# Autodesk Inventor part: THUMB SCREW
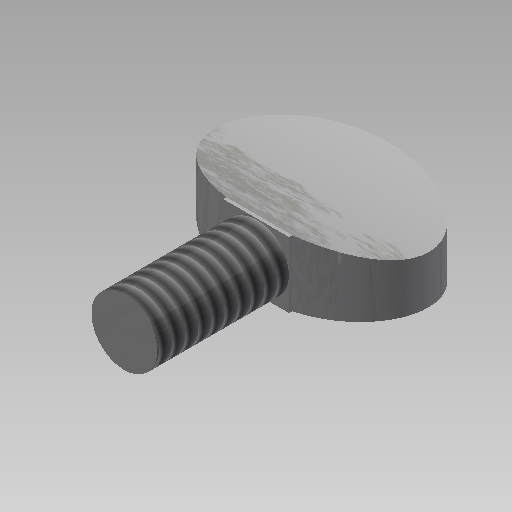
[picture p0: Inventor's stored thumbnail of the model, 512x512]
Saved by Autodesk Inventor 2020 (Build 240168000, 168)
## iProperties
Part Number: THUMB SCREW
Document SubType Name: Modeling
Created: 2003-11
Designer: Autodesk, Inc.
Manufacturer: Standard
Standards Organization: Custom
Mass: 11.3543 g
Surface Area: 9.71998 cm^2
Volume: 1.44641 cm^3
Density: 7.85 g/cm^3
Material: Steel, Mild
Appearance: Steel
Control State: 0
Master: False
Checked Out: False
Shininess: 64.0
Length Units: 11272
Angle Units: 11279
Time Units: 11290
Mass Units: 11286
Length Display Precision: 3
Angle Display Precision: 2
Compacted: True
Density: 0.0
Volumn: 0.0
Area: 0.0
PropertySet Name: Model Information
Author: Autodesk, Inc.
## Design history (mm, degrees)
sketch "Sketch1"
  geometry: C1 r 3.175 at (0, 0); 1 further point
  constraints: 1 centre point, 1 coincident
  dimensions: "d0" = 6.35 diameter of C1
extrude "Extrusion1" new body sketch "Sketch1" distance "d1" = 12.7; taper "d2" = 0 deg
sketch "Sketch2"
  geometry: L1 (-10.312, 3.175)-(10.312, 3.175); L2 (10.312, 3.175)-(10.312, -3.175); L3 (10.312, -3.175)-(-10.312, -3.175); L4 (-10.312, -3.175)-(-10.312, 3.175); C1 r 3.175 at (0, 0) reference; 1 further point
  constraints: 8 end point, 2 parallel, 1 horizontal, 1 perpendicular
  dimensions: "d3" = 3.175 distance from line of L3 point (0, 0); "d4" = 3.175 distance from line of point (0, 0) L1; "d5" = 20.6248 distance between parallel lines of L2 L4; "d6" = 10.3124 distance from line of L4 point (0, 0) (= 0.5 x d5)
extrude "Extrusion2" join sketch "Sketch2" distance "d7" = 12.7; taper "d8" = 0 deg
sketch "Sketch3"
  geometry: L1 (20.625, 12.7)-(0, 12.7) reference; L2 (0, 0)-(0, 12.7) reference; L3 (10.312, 0)-(0, 0) reference; L4 (20.625, 0)-(10.312, 0) reference; L5 (20.625, 0)-(20.625, 12.7) reference; L6 (10.312, 12.7)-(10.312, 0); L7 (0, 6.35)-(20.625, 6.35); L8 (7.137, 0)-(7.137, -12.7) reference; L9 (13.487, 0)-(13.487, -12.7) reference; L10 (7.137, 0)-(7.137, 0.308); L11 (13.487, 0)-(13.487, 0.308); 1 further point
  constraints: 8 end point, 4 midpoint, 3 vertical, 1 parallel, 6 other
extrude "Extrusion3" cut sketch "Sketch3" distance "d9" = 12.7; taper "d10" = 0 deg
workplane "Work Plane1"
sketch "Sketch4"
  geometry: L1 (-3.175, -0.308)-(-3.175, -0.308) reference; L2 (3.175, -0.308)-(-3.175, -0.308) reference; L3 (3.175, -0.308)-(3.175, -0.308) reference; L4 (3.175, -0.308)-(-3.175, -0.308) reference; L5 (-3.175, -0.308)-(-3.175, -12.7) reference; L6 (3.175, -12.7)-(3.175, -0.308) reference; L7 (3.175, -12.7)-(3.175, -0.308); L8 (-3.175, -0.308)-(-3.175, -12.7); A1 r 22.382 centre (-24.682, -6.504) between (-3.175, -12.7) and (-3.175, -0.308); A2 r 22.382 centre (24.682, -6.504) between (3.175, -0.308) and (3.175, -12.7)
  constraints: 4 end point, 4 point on circle, 2 centre point, 2 equal length
  dimensions: "d12" = 22.38154 radius of A1; "d13" = 22.38154 radius of A2 (= d12)
extrude "Extrusion4" cut sketch "Sketch4" distance "d14" = 25.4; taper "d15" = 0 deg
thread "Thread1" dims "d16" = 25.4, "d17" = 0
body "Solid1"
node "Projected Loop1"
node "Projected Loop2"
other parameters: "d11" = -12.7
